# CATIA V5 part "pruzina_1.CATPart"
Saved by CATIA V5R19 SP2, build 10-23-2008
Part number: Pruzina delka 22mm
Bounding box of the stored display mesh (mm): x -8 to 8, y -8 to 8, z 0 to 22
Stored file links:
  D:\DURATEC\pruzina_1.CATPart
  D:\DURATEC\Pohyb pruziny.CATProduct
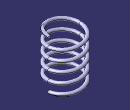
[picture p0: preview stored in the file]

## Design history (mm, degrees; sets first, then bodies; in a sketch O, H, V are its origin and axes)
External parameters (linked from other documents)
  `External.Delka pruziny` = 22 mm
  `External.Pocet zavitu` = 5
  `External.Vnitrni prumer pruziny` = 13 mm
  `External.Prumer dratu` = 1.5 mm
Set1
  Plane1: type Normal, Curve {line type PtDir, Direction (0, 0, 1), Start 0, End 22 {= `External.Delka pruziny`}, RefPoint {point type Coord, X 0, Y 0, Z 0}}, RefPoint vertex of Plane1
  Sketch1 on zx-plane, origin (0, 0, 0), H (-1, 0, 0), V (0, 0, 1)
    line L1 (6.5, 21) -> (6.5, 16)
    construction line L2 (6.5, 16) -> (-6.5, 16)
    line L3 (-6.5, 16) -> (-6.5, 21)
    construction line L4 (-6.5, 21) -> (6.5, 21)
    reference intersected line E1 through (0, 22) direction (-1, 0) from Plane1
    distance L3 L1 = 13 {= `External.Vnitrni prumer pruziny`}
    length L1 = 5
    distance L4 E1 = 1
    vertical: L1 V, L3 V
    horizontal: L2 H, L4 H
    equidistance: L1 L3 O
  Line1: type PtDir, Direction (0, 0, 1), Start 0, End 22 {= `External.Delka pruziny`}, RefPoint {point type Coord, X 0, Y 0, Z 0}
Body1 "Pruzina" (main body)
  Helix1: Pitch 4.4 {= `External.Delka pruziny` /`External.Pocet zavitu`}, TaperAngle 0, Height 22 {= Plane1.End}, Direction {line type PtDir, Direction (0, 0, 1), Start 0, End 22 {= `External.Delka pruziny`}, RefPoint {point type Coord, X 0, Y 0, Z 0}}, RefPoint {point type Coord, X 7.25 {= `External.Vnitrni prumer pruziny` /2+`External.Prumer dratu` /2}, Y 0, Z 0}
  Sketch2 on zx-plane, origin (0, 0, 0), H (-1, 0, 0), V (0, 0, 1)
    circle A1 centre (-7.25, 0) radius 0.75
    point P1 (-7.25, 0)
    reference projected point E1 (-7.25, 0) from vertex of Helix1
    radius A1 = 0.75 {= `External.Prumer dratu` /2}
    distance V A1 = 6.5 (reference)
    distance V A1 = 8 (reference)
    coincidence: P1 E1
  Rib1: profile Sketch2, centre curve Helix1
  Split1: SplitPlane xy-plane
  Split2: SplitPlane Plane1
